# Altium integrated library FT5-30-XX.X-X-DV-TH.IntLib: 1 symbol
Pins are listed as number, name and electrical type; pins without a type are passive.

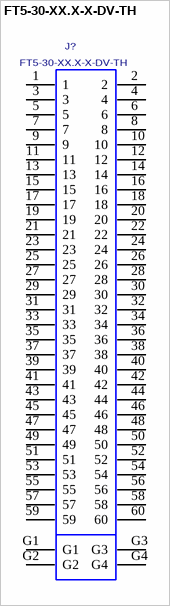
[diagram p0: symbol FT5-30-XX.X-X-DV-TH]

## FT5-30-XX.X-X-DV-TH
designator J?
FT5 TERMINAL ASSEMBLY, 60 PINS.; MANUFACTURER: SAMTEC
footprint FT5-30-XX.X-X-DV-TH
pins: 1, 2, 3, 4, 5, 6, 7, 8, 9, 10, 11, 12, 13, 14, 15, 16, 17, 18, 19, 20, 21, 22, 23, 24, 25, 26, 27, 28, 29, 30, 31, 32, 33, 34, 35, 36, 37, 38, 39, 40, 41, 42, 43, 44, 45, 46, 47, 48, 49, 50, 51, 52, 53, 54, 55, 56, 57, 58, 59, 60, G1, G2, G3, G4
